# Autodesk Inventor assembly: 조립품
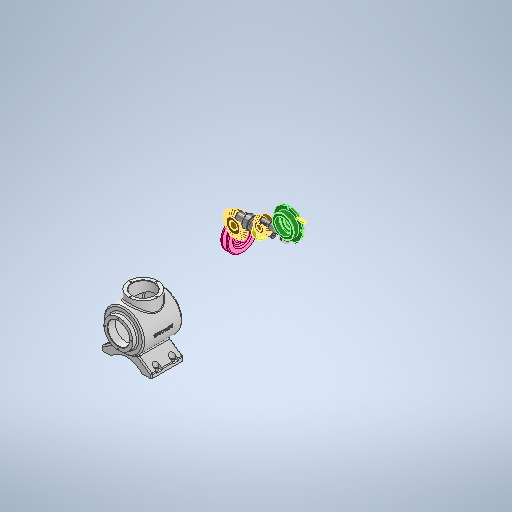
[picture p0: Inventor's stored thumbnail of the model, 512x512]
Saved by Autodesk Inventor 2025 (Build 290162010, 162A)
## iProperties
Created: 2024-07
Part Number: 조립품
Document SubType Name: Assembly
Designer: 학생
Author: 학생
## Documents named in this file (15)
- C:\Users\학생\Desktop\740709V1011\조립품.iam
- C:\Users\학생\Desktop\740709V1011\본체.ipt
- C:\Users\학생\Desktop\740709V1011\V-벨트풀리\V-벨트풀리.ipt
- C:\Users\학생\Desktop\740709V1011\메인 베벨기어\메인 베벨기어.ipt
- C:\Users\학생\Desktop\740709V1011\메인 축\메인 축.ipt
- C:\Users\학생\Desktop\740709V1011\베어링 6203\베어링 6203.ipt
- C:\Users\학생\Desktop\740709V1011\볼트 M4 x 10\볼트 M4 x 10.ipt
- C:\Users\학생\Desktop\740709V1011\서브 베벨기어\서브 베벨기어.ipt
- C:\Users\학생\Desktop\740709V1011\서브 축\서브 축.ipt
- C:\Users\학생\Desktop\740709V1011\오일실 17 x 32 x 8\오일실 17 x 32 x 8.ipt
- C:\Users\학생\Desktop\740709V1011\와셔 4 x 16\와셔 4 x 16.ipt
- C:\Users\학생\Desktop\740709V1011\육각볼트 M4 x 8\육각볼트 M4 x 8.ipt
- C:\Users\학생\Desktop\740709V1011\커버\커버.ipt
- C:\Users\학생\Desktop\740709V1011\키 4 x 4 x 14\키 4 x 4 x 14.ipt
- C:\Users\학생\Desktop\740709V1011\키 5 x 5 x 14\키 5 x 5 x 14.ipt
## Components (1 placed, 1 different names)
1. V-벨트풀리:1
